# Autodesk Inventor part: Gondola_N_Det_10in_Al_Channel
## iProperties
Shininess: 64.0
Length Units: 11272
Angle Units: 11279
Time Units: 11290
Mass Units: 11286
Length Display Precision: 3
Angle Display Precision: 2
Compacted: True
Part Number: Gondola_N_Det_10in_Al_Channel
Document SubType Name: Modeling
Created: 2004-12
Designer: John Blackburn
Material: Aluminum-6061
Description: AL. Assoc. 8" 6061-T6 Channel
Manufacturer: Standard
Standards Organization: Custom
Density: 0.0
Volumn: 0.0
Area: 0.0
PropertySet Name: Model Information
Control State: 0
Master: False
Checked Out: False
Author: John Blackburn
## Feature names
1. Extrusion1
2. Hole1
3. Hole2
4. Hole3
5. Hole4
6. Hole5
7. Hole6
